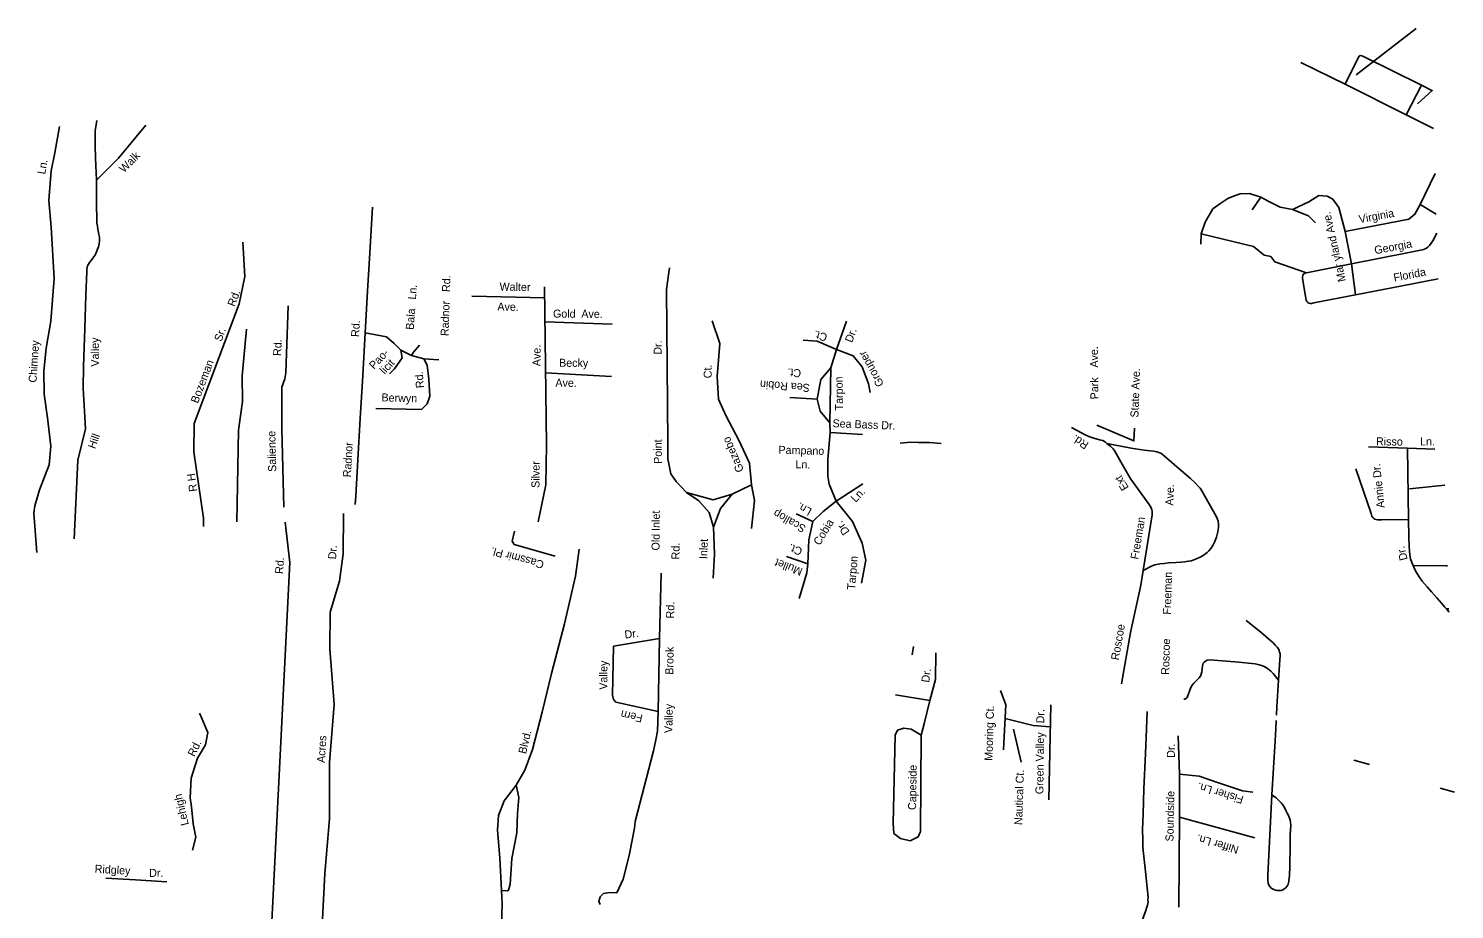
# Model space of a CAD drawing. Extents: x 2308163 to 2335412, y -96774 to 127732.
# Drawn here: x 2322562.54 to 2322608.21, y 95031.9 to 95060.1 of the extents above; entities that cross this region are included whole.
import ezdxf

# ---------------------------------------------------------------- set-up
doc = ezdxf.new("R2010")
doc.units = 0
doc.layers.add('Old_Level_10', color=7, linetype='Continuous')
doc.layers.add('Old_Level_35', color=7, linetype='Continuous')

msp = doc.modelspace()

# ---------------------------------------------------------------- linework, layer by layer
at = {"layer": 'Old_Level_10'}
for points in [[(2322606.977, 95060.101), (2322605.057, 95058.622)], [(2322607.499, 95058.133), (2322607.023, 95057.695)], [(2322597.956, 95047.306), (2322597.942, 95046.903), (2322596.749, 95047.408)], [(2322594.328, 95036.621), (2322594.082, 95037.677)]]:
    msp.add_lwpolyline(points, dxfattribs=at)
at = {"layer": 'Old_Level_35'}
for p, q in [((2322603.287, 95059.019), (2322604.701, 95058.32)), ((2322604.701, 95058.32), (2322606.662, 95057.336)), ((2322606.662, 95057.336), (2322607.153, 95058.284)), ((2322607.499, 95058.111), (2322607.153, 95058.284)), ((2322607.538, 95056.896), (2322606.662, 95057.336)), ((2322605.038, 95051.582), (2322604.905, 95052.57)), ((2322568.145, 95044.429), (2322567.842, 95046.55)), ((2322606.733, 95044.389), (2322606.7, 95046.667)), ((2322573.007, 95044.865), (2322573.023, 95045.135)), ((2322568.146, 95044.162), (2322568.145, 95044.429)), ((2322590.842, 95040.059), (2322590.879, 95040.323)), ((2322602.519, 95038.388), (2322602.567, 95039.244)), ((2322598.354, 95037.976), (2322598.364, 95038.242)), ((2322602.504, 95038.124), (2322602.519, 95038.388)), ((2322598.343, 95037.689), (2322598.354, 95037.976)), ((2322602.492, 95037.948), (2322602.481, 95037.684)), ((2322602.465, 95037.3), (2322602.362, 95035.575)), ((2322602.481, 95037.684), (2322602.465, 95037.3)), ((2322605.488, 95036.548), (2322604.983, 95036.677)), ((2322608.207, 95035.662), (2322607.752, 95035.79))]:
    msp.add_line(p, q, dxfattribs=at)
for points in [[(2322607.153, 95058.284), (2322605.292, 95059.204), (2322605.237, 95059.232), (2322605.191, 95059.24), (2322605.152, 95059.216), (2322605.136, 95059.184), (2322604.701, 95058.32)], [(2322563.389, 95056.118), (2322563.538, 95056.965)], [(2322564.722, 95055.246), (2322564.693, 95055.95), (2322564.68, 95056.364), (2322564.675, 95056.536), (2322564.683, 95056.825), (2322564.73, 95057.152)], [(2322566.305, 95057.013), (2322565.427, 95055.948), (2322564.722, 95055.246)], [(2322562.806, 95043.331), (2322562.714, 95044.588), (2322562.742, 95044.825), (2322562.899, 95045.335), (2322563.204, 95046.137), (2322563.264, 95046.729), (2322563.157, 95047.645), (2322563.044, 95048.401), (2322563.03, 95049.135), (2322563.114, 95049.865), (2322563.263, 95050.732), (2322563.37, 95052.096), (2322563.268, 95053.744), (2322563.198, 95054.599), (2322563.271, 95055.547), (2322563.389, 95056.118)], [(2322564.289, 95048.587), (2322564.305, 95049.284), (2322564.343, 95050.503), (2322564.376, 95051.571), (2322564.41, 95052.313), (2322564.411, 95052.4), (2322564.417, 95052.453), (2322564.43, 95052.509), (2322564.463, 95052.562), (2322564.497, 95052.608), (2322564.551, 95052.678), (2322564.608, 95052.755), (2322564.663, 95052.837), (2322564.707, 95052.922), (2322564.755, 95053.04), (2322564.781, 95053.118), (2322564.802, 95053.208), (2322564.813, 95053.29), (2322564.813, 95053.355), (2322564.812, 95053.422), (2322564.8, 95053.504), (2322564.789, 95053.57), (2322564.764, 95053.675), (2322564.749, 95053.77), (2322564.737, 95053.878), (2322564.722, 95054.573), (2322564.722, 95055.246)], [(2322607.097, 95054.447), (2322607.583, 95055.462)], [(2322604.905, 95052.57), (2322604.706, 95053.601), (2322604.5, 95054.371), (2322604.311, 95054.643), (2322604.131, 95054.732), (2322603.867, 95054.758), (2322603.544, 95054.553), (2322603.022, 95054.306), (2322602.626, 95054.386), (2322602.267, 95054.564), (2322602.007, 95054.706), (2322601.646, 95054.818), (2322601.347, 95054.811), (2322601.129, 95054.736), (2322600.944, 95054.659), (2322600.689, 95054.486), (2322600.468, 95054.328), (2322600.221, 95053.905), (2322600.092, 95053.529), (2322600.08, 95053.197)], [(2322602.007, 95054.706), (2322601.728, 95054.301)], [(2322573.023, 95045.135), (2322573.089, 95046.296), (2322573.167, 95047.623), (2322573.249, 95048.997), (2322573.328, 95050.362), (2322573.399, 95051.697), (2322573.476, 95052.922), (2322573.557, 95054.384)], [(2322603.022, 95054.306), (2322603.529, 95054.106), (2322603.754, 95053.883)], [(2322604.706, 95053.601), (2322606.75, 95053.995), (2322606.938, 95054.154), (2322607.097, 95054.447)], [(2322607.624, 95054.157), (2322607.107, 95054.467)], [(2322567.842, 95046.55), (2322567.849, 95047.455), (2322569.293, 95051.291), (2322569.467, 95052.166), (2322569.409, 95053.265)], [(2322600.092, 95053.529), (2322601.77, 95053.123), (2322602.109, 95052.846), (2322602.323, 95052.805), (2322602.45, 95052.635), (2322603.463, 95052.279)], [(2322604.905, 95052.57), (2322606.688, 95052.926), (2322607.065, 95052.995), (2322607.168, 95053.016), (2322607.215, 95053.03), (2322607.27, 95053.053), (2322607.306, 95053.074), (2322607.349, 95053.105), (2322607.402, 95053.154), (2322607.461, 95053.227), (2322607.51, 95053.304), (2322607.643, 95053.55)], [(2322584.467, 95042.511), (2322584.516, 95043.277), (2322584.478, 95044.135), (2322584.336, 95044.614), (2322584.01, 95044.987), (2322583.613, 95045.249), (2322583.286, 95045.598), (2322583.114, 95045.852), (2322583.018, 95046.33), (2322583.013, 95046.849), (2322582.979, 95051.747), (2322583.04, 95052.219), (2322583.071, 95052.443)], [(2322605.038, 95051.582), (2322603.703, 95051.318), (2322603.624, 95051.303), (2322603.589, 95051.303), (2322603.547, 95051.313), (2322603.515, 95051.329), (2322603.477, 95051.361), (2322603.453, 95051.401), (2322603.339, 95052.1), (2322603.34, 95052.154), (2322603.349, 95052.193), (2322603.365, 95052.232), (2322603.381, 95052.25), (2322603.422, 95052.271), (2322603.463, 95052.279), (2322604.905, 95052.57)], [(2322607.689, 95052.088), (2322606.53, 95051.866), (2322605.038, 95051.582)], [(2322576.743, 95051.533), (2322579.074, 95051.476)], [(2322578.865, 95044.306), (2322579.109, 95045.494), (2322579.131, 95046.78), (2322579.07, 95051.829)], [(2322570.716, 95044.779), (2322570.655, 95047.286), (2322570.656, 95048.618), (2322570.756, 95048.885), (2322570.785, 95049.076), (2322570.859, 95051.229)], [(2322579.084, 95050.708), (2322581.229, 95050.634)], [(2322585.699, 95045.492), (2322585.633, 95046.194), (2322585.296, 95046.906), (2322584.872, 95047.71), (2322584.642, 95048.237), (2322584.599, 95048.961), (2322584.681, 95050.018), (2322584.435, 95050.749)], [(2322588.409, 95044.97), (2322588.179, 95045.52), (2322588.143, 95045.769), (2322588.139, 95046.311), (2322588.214, 95047.166), (2322588.202, 95047.482), (2322588.24, 95049.241), (2322588.418, 95049.822), (2322588.743, 95050.736)], [(2322569.212, 95044.314), (2322569.265, 95047.244), (2322569.398, 95048.165), (2322569.382, 95048.989), (2322569.523, 95050.473)], [(2322573.328, 95050.362), (2322574.011, 95050.228), (2322574.252, 95050.017), (2322574.471, 95049.806), (2322574.507, 95049.557), (2322574.269, 95049.204), (2322574.106, 95049.052)], [(2322588.418, 95049.822), (2322587.795, 95050.092), (2322587.345, 95050.13)], [(2322574.471, 95049.806), (2322574.803, 95049.637), (2322574.875, 95049.747), (2322575.059, 95049.97)], [(2322574.803, 95049.637), (2322575.206, 95049.533), (2322575.679, 95049.494)], [(2322588.418, 95049.822), (2322588.953, 95049.623), (2322589.235, 95049.275), (2322589.442, 95048.726), (2322589.5, 95048.453)], [(2322575.206, 95049.533), (2322575.312, 95049.326), (2322575.364, 95048.873), (2322575.391, 95048.33), (2322575.314, 95048.085), (2322575.128, 95047.911), (2322573.661, 95047.939)], [(2322588.24, 95049.241), (2322587.911, 95048.869), (2322587.799, 95048.241), (2322587.899, 95047.854), (2322588.202, 95047.482)], [(2322579.103, 95049.083), (2322581.216, 95048.963)], [(2322564.289, 95048.587), (2322564.374, 95047.286), (2322564.121, 95046.284), (2322564.004, 95043.765)], [(2322587.799, 95048.241), (2322586.92, 95048.294)], [(2322595.939, 95047.329), (2322596.378, 95047.1), (2322596.495, 95047.043), (2322596.658, 95046.991), (2322596.835, 95046.94), (2322596.944, 95046.914), (2322597.03, 95046.866), (2322597.075, 95046.817)], [(2322588.214, 95047.166), (2322589.25, 95047.108)], [(2322591.766, 95046.823), (2322591.391, 95046.846), (2322591.035, 95046.849), (2322590.789, 95046.857), (2322590.461, 95046.829)], [(2322598.236, 95042.757), (2322598.529, 95044.54), (2322598.53, 95044.587), (2322598.523, 95044.648), (2322598.517, 95044.698), (2322598.509, 95044.73), (2322598.497, 95044.761), (2322598.428, 95044.869), (2322597.844, 95045.681), (2322597.74, 95045.856), (2322597.523, 95046.235), (2322597.387, 95046.473), (2322597.335, 95046.569), (2322597.275, 95046.648), (2322597.205, 95046.721), (2322597.075, 95046.817)], [(2322597.075, 95046.817), (2322597.854, 95046.673), (2322598.274, 95046.609), (2322598.57, 95046.571), (2322598.679, 95046.552), (2322598.741, 95046.535), (2322598.802, 95046.508), (2322598.85, 95046.478), (2322598.918, 95046.414), (2322599.393, 95046.003), (2322599.752, 95045.698), (2322599.905, 95045.561), (2322599.99, 95045.466), (2322600.058, 95045.386), (2322600.119, 95045.307), (2322600.208, 95045.132), (2322600.494, 95044.64), (2322600.575, 95044.49), (2322600.605, 95044.415), (2322600.635, 95044.341), (2322600.653, 95044.237), (2322600.653, 95044.137), (2322600.643, 95044.059), (2322600.632, 95043.988), (2322600.588, 95043.82), (2322600.524, 95043.663), (2322600.467, 95043.555), (2322600.41, 95043.47), (2322600.337, 95043.378), (2322600.29, 95043.332), (2322600.249, 95043.295), (2322600.158, 95043.23), (2322600.067, 95043.181), (2322599.967, 95043.133), (2322599.858, 95043.09), (2322599.789, 95043.066), (2322599.683, 95043.047), (2322599.572, 95043.029), (2322599.45, 95043.022), (2322599.29, 95043.012), (2322599.047, 95042.994), (2322598.914, 95042.982), (2322598.771, 95042.962), (2322598.615, 95042.934), (2322598.528, 95042.906), (2322598.236, 95042.757)], [(2322605.457, 95046.71), (2322606.7, 95046.667)], [(2322606.7, 95046.667), (2322607.578, 95046.636)], [(2322606.733, 95044.389), (2322605.872, 95044.378), (2322605.778, 95044.373), (2322605.748, 95044.374), (2322605.7, 95044.383), (2322605.657, 95044.394), (2322605.625, 95044.413), (2322605.587, 95044.45), (2322605.563, 95044.495), (2322605.542, 95044.574), (2322605.052, 95046.009)], [(2322584.478, 95044.135), (2322584.702, 95044.737), (2322585.079, 95045.198), (2322585.699, 95045.492), (2322585.795, 95044.993), (2322585.696, 95044.093)], [(2322588.409, 95044.97), (2322589.264, 95045.528)], [(2322607.897, 95045.486), (2322606.771, 95045.371)], [(2322583.613, 95045.249), (2322584.463, 95045.016), (2322585.079, 95045.198)], [(2322571.775, 95028.028), (2322572.034, 95033.059), (2322572.18, 95034.801), (2322572.185, 95036.605), (2322572.335, 95038.461), (2322572.196, 95040.242), (2322572.208, 95041.415), (2322572.5, 95042.408), (2322572.616, 95043.291), (2322572.632, 95044.58)], [(2322587.504, 95042.97), (2322587.531, 95043.737), (2322587.664, 95044.319), (2322587.13, 95044.563)], [(2322587.664, 95044.319), (2322587.991, 95044.646), (2322588.409, 95044.97), (2322588.928, 95044.32), (2322589.243, 95043.633), (2322589.36, 95043.087), (2322589.222, 95042.347)], [(2322570.18, 95028.329), (2322570.916, 95043.006), (2322570.76, 95044.3)], [(2322606.884, 95042.908), (2322606.84, 95043.011), (2322606.803, 95043.129), (2322606.782, 95043.239), (2322606.763, 95043.38), (2322606.751, 95043.513), (2322606.742, 95043.827), (2322606.733, 95044.389)], [(2322579.407, 95043.215), (2322578.094, 95043.587), (2322578.032, 95043.687), (2322578.102, 95044.017)], [(2322578.457, 95026.574), (2322578.225, 95026.974), (2322578.065, 95027.094), (2322577.711, 95029.152), (2322577.68, 95029.693), (2322577.656, 95030.414), (2322577.713, 95032.081), (2322577.695, 95032.507), (2322577.633, 95033.556), (2322577.566, 95034.442), (2322577.598, 95034.916), (2322577.778, 95035.384), (2322578.155, 95035.878), (2322578.434, 95036.359), (2322578.686, 95037.022), (2322578.99, 95038.222), (2322579.294, 95039.455), (2322579.709, 95041.044), (2322580.056, 95042.57), (2322580.175, 95043.432)], [(2322587.217, 95041.852), (2322587.472, 95042.678), (2322587.504, 95042.97), (2322586.812, 95043.197)], [(2322597.539, 95039.123), (2322597.828, 95040.773), (2322598.161, 95042.281), (2322598.236, 95042.757)], [(2322608.025, 95041.42), (2322608.021, 95041.427), (2322607.953, 95041.523), (2322607.892, 95041.594), (2322607.794, 95041.705), (2322607.641, 95041.874), (2322607.475, 95042.066), (2322607.337, 95042.226), (2322607.174, 95042.411), (2322607.08, 95042.551), (2322606.989, 95042.694), (2322606.929, 95042.805), (2322606.884, 95042.908)], [(2322607.978, 95042.906), (2322607.939, 95042.906), (2322606.884, 95042.908)], [(2322582.798, 95042.663), (2322582.752, 95040.573), (2322581.278, 95040.329), (2322581.248, 95038.759), (2322581.276, 95038.619), (2322581.355, 95038.535), (2322582.712, 95038.242), (2322582.752, 95040.573)], [(2322607.953, 95041.523), (2322608.022, 95041.528)], [(2322602.567, 95039.244), (2322602.615, 95039.908), (2322602.624, 95040.024), (2322602.623, 95040.083), (2322602.608, 95040.143), (2322602.59, 95040.197), (2322602.567, 95040.247), (2322602.529, 95040.301), (2322602.478, 95040.357), (2322602.401, 95040.437), (2322602.323, 95040.501), (2322602.002, 95040.775), (2322601.535, 95041.153)], [(2322591.598, 95040.117), (2322591.587, 95039.265), (2322591.407, 95038.595), (2322590.31, 95038.774)], [(2322599.542, 95038.632), (2322599.567, 95038.636), (2322599.595, 95038.65), (2322599.622, 95038.667), (2322599.642, 95038.69), (2322599.662, 95038.72), (2322599.688, 95038.806), (2322599.72, 95038.89), (2322599.755, 95038.983), (2322599.812, 95039.083), (2322599.86, 95039.146), (2322599.948, 95039.236), (2322600.028, 95039.321), (2322600.069, 95039.375), (2322600.096, 95039.437), (2322600.12, 95039.514), (2322600.129, 95039.607), (2322600.142, 95039.699), (2322600.149, 95039.743), (2322600.159, 95039.782), (2322600.19, 95039.821), (2322600.236, 95039.856), (2322600.284, 95039.878), (2322600.347, 95039.891), (2322600.511, 95039.879), (2322601.299, 95039.814), (2322601.72, 95039.773), (2322601.829, 95039.762), (2322601.954, 95039.737), (2322602.031, 95039.71), (2322602.117, 95039.677), (2322602.214, 95039.615), (2322602.328, 95039.526), (2322602.4, 95039.454), (2322602.567, 95039.244)], [(2322593.673, 95038.91), (2322593.844, 95038.448), (2322593.763, 95037.018)], [(2322568.019, 95038.19), (2322568.037, 95038.149), (2322568.283, 95037.572), (2322568.213, 95037.175), (2322567.95, 95036.746), (2322567.757, 95036.106), (2322567.716, 95035.48), (2322567.763, 95035.193), (2322567.821, 95034.639), (2322567.901, 95034.218), (2322567.792, 95033.803)], [(2322582.712, 95038.242), (2322582.69, 95037.605), (2322582.631, 95037.329), (2322582.562, 95036.979), (2322581.968, 95034.722), (2322581.945, 95034.502), (2322581.785, 95033.681), (2322581.756, 95033.543), (2322581.585, 95032.87), (2322581.382, 95032.435), (2322581.161, 95032.443), (2322580.955, 95032.409), (2322580.845, 95032.307), (2322580.808, 95032.161), (2322580.853, 95032.061)], [(2322591.407, 95038.595), (2322591.223, 95037.845), (2322591.132, 95037.486), (2322591.105, 95034.401), (2322591.036, 95034.231), (2322590.779, 95034.098), (2322590.467, 95034.172), (2322590.252, 95034.336), (2322590.231, 95034.652), (2322590.297, 95037.484), (2322590.366, 95037.639), (2322590.573, 95037.71), (2322590.808, 95037.671), (2322591.132, 95037.486)], [(2322595.22, 95035.409), (2322595.276, 95038.45)], [(2322593.819, 95038.011), (2322594.719, 95037.788), (2322595.263, 95037.751)], [(2322598.187, 95031.42), (2322598.206, 95031.486), (2322598.232, 95031.602), (2322598.257, 95031.704), (2322598.308, 95031.842), (2322598.351, 95031.974), (2322598.376, 95032.045), (2322598.385, 95032.099), (2322598.394, 95032.145), (2322598.387, 95032.215), (2322598.397, 95032.294), (2322598.366, 95032.6), (2322598.316, 95033.117), (2322598.251, 95033.697), (2322598.225, 95033.893), (2322598.223, 95034.15), (2322598.215, 95034.455), (2322598.235, 95034.963), (2322598.262, 95035.76), (2322598.312, 95036.891), (2322598.343, 95037.689)], [(2322599.399, 95036.237), (2322599.359, 95037.465)], [(2322578.155, 95035.878), (2322578.24, 95035.486), (2322578.206, 95034.98), (2322578.185, 95034.359), (2322578.025, 95033.53), (2322577.964, 95032.714), (2322577.909, 95032.519), (2322577.875, 95032.504), (2322577.695, 95032.507)], [(2322599.385, 95031.977), (2322599.402, 95034.861), (2322599.399, 95036.237)], [(2322599.399, 95036.237), (2322600.027, 95036.165), (2322600.617, 95035.963), (2322601.421, 95035.703), (2322601.751, 95035.658)], [(2322602.362, 95035.575), (2322602.229, 95032.999), (2322602.229, 95032.847), (2322602.239, 95032.746), (2322602.267, 95032.678), (2322602.3, 95032.631), (2322602.341, 95032.589), (2322602.374, 95032.566), (2322602.421, 95032.54), (2322602.472, 95032.523), (2322602.528, 95032.508), (2322602.577, 95032.505), (2322602.607, 95032.507), (2322602.653, 95032.515), (2322602.687, 95032.526), (2322602.738, 95032.548), (2322602.774, 95032.572), (2322602.805, 95032.595), (2322602.838, 95032.633), (2322602.862, 95032.671), (2322602.878, 95032.709), (2322602.892, 95032.759), (2322602.9, 95032.796), (2322602.907, 95032.844), (2322602.915, 95032.896), (2322602.924, 95032.99), (2322602.926, 95033.1), (2322602.929, 95033.169), (2322602.942, 95034.069), (2322602.947, 95034.296), (2322602.957, 95034.456), (2322602.963, 95034.592), (2322602.956, 95034.702), (2322602.941, 95034.758), (2322602.922, 95034.827), (2322602.891, 95034.91), (2322602.853, 95034.986), (2322602.81, 95035.073), (2322602.77, 95035.143), (2322602.706, 95035.248), (2322602.653, 95035.319), (2322602.606, 95035.375), (2322602.496, 95035.472), (2322602.362, 95035.575)], [(2322599.402, 95034.861), (2322601.817, 95034.197)], [(2322565.02, 95032.91), (2322565.969, 95032.854), (2322566.976, 95032.785)]]:
    msp.add_lwpolyline(points, dxfattribs=at)

# ---------------------------------------------------------------- texts
at = {"layer": 'Old_Level_10'}
for s, height, rotation, p in [('Walk', 0.2563, 45.3872, (2322565.601, 95055.467)), ('Ln.', 0.2563, 80.1858, (2322563.076, 95055.421)), ('Mar yland Ave.', 0.25632, 102.8292, (2322604.731, 95052.023)), ('Virginia', 0.2563, 10.4931, (2322605.167, 95053.869)), ('Georgia', 0.2563, 10.4813, (2322605.665, 95052.875)), ('Florida', 0.2563, 11.0089, (2322606.281, 95051.998)), ('Bala   Ln.', 0.2563, 85.7542, (2322574.877, 95050.45)), ('Radnor   Rd.', 0.25632, 88.1523, (2322575.994, 95050.254)), ('Walter', 0.2563, 358.7381, (2322577.625, 95051.716)), ('Bozeman       Sr.        Rd.', 0.25632, 69.1948, (2322567.968, 95048.084)), ('Ave.', 0.2563, 358.7381, (2322577.556, 95051.076)), ('Gold', 0.2563, 359.4093, (2322579.338, 95050.849)), ('Ave.', 0.2563, 359.4093, (2322580.245, 95050.842)), ('Rd.', 0.2563, 86.9357, (2322573.128, 95050.222)), ('Chimney', 0.2563, 86.2486, (2322562.799, 95048.761)), ('Valley', 0.2563, 90.4143, (2322564.803, 95049.28)), ('Rd.', 0.2563, 87.6086, (2322570.632, 95049.615)), ('Dr.', 0.2563, 89.4605, (2322582.818, 95049.66)), ('Ct.', 0.2563, 163.8283, (2322588.146, 95050.322)), ('Dr.', 0.2563, 69.3849, (2322588.915, 95050.029)), ('Pao-', 0.2563, 46.9069, (2322573.61, 95049.173)), ('Ave.', 0.2563, 89.5229, (2322578.938, 95049.292)), ('Grouper', 0.2563, 119.423, (2322589.947, 95048.718)), ('Ave.', 0.2563, 90.5704, (2322596.796, 95049.248)), ('licit', 0.2563, 46.9069, (2322573.949, 95049.014)), ('Becky', 0.2563, 359.3952, (2322579.533, 95049.276)), ('Ct.', 0.2563, 91.0081, (2322584.423, 95048.907)), ('Ct.', 0.2563, 175.7151, (2322587.293, 95049.19)), ('State Ave.', 0.2563, 88.0247, (2322598.084, 95047.646)), ('Rd.', 0.2563, 94.3165, (2322575.208, 95048.599)), ('Ave.', 0.2563, 359.3952, (2322579.415, 95048.636)), ('       Sea Robin ', 0.25632, 175.7151, (2322588.237, 95048.669)), ('Tarpon', 0.2563, 90.9688, (2322588.63, 95047.878)), ('Park', 0.2563, 90.5704, (2322596.806, 95048.232)), ('Berwyn', 0.2563, 358.1695, (2322573.844, 95048.168)), ('Sea Bass Dr.', 0.25632, 357.7622, (2322588.286, 95047.34)), ('Hill ', 0.2563, 70.5702, (2322564.679, 95046.629)), ('Salience', 0.2563, 91.3925, (2322570.477, 95045.913)), ('Radnor', 0.2563, 86.7192, (2322572.864, 95045.731)), ('Point', 0.2563, 90.4182, (2322582.826, 95046.168)), ('Gazebo', 0.2563, 113.0823, (2322585.459, 95045.96)), ('Rd.', 0.2563, 147.5672, (2322596.515, 95046.831)), ('Risso', 0.2563, 359.2312, (2322605.693, 95046.761)), ('Ln.', 0.2563, 359.7872, (2322607.106, 95046.758)), ('Pampano ', 0.2563, 358.5677, (2322586.557, 95046.489)), ('Silver', 0.2563, 89.5225, (2322578.905, 95045.395)), ('Ln.', 0.2563, 358.5677, (2322587.101, 95046.027)), ('Annie Dr.', 0.2563, 96.0826, (2322605.973, 95044.765)), ('R H', 0.2563, 97.6871, (2322567.945, 95045.292)), ('Ext', 0.2563, 120.8787, (2322597.786, 95045.404)), ('Ave.', 0.2563, 88.3651, (2322599.204, 95044.827)), ('Ln.', 0.2563, 45.7345, (2322589.028, 95044.915)), ('Old Inlet', 0.2563, 89.4837, (2322582.751, 95043.392)), ('Scallop ', 0.2563, 150.3852, (2322587.463, 95044.167)), ('Ln.', 0.2563, 150.3852, (2322587.652, 95044.715)), ('Cobia', 0.2563, 58.9524, (2322587.881, 95043.536)), ('Dr.', 0.2563, 125.5361, (2322588.85, 95043.998)), ('Freeman', 0.2563, 80.6561, (2322598.081, 95043.095)), ('Inlet', 0.2563, 88.0247, (2322584.277, 95043.115)), ('Dr.', 0.2563, 85.9893, (2322572.391, 95043.105)), ('Cassmir Pl.', 0.25632, 164.8672, (2322579.071, 95043.049)), ('Rd.', 0.2563, 89.4837, (2322583.389, 95043.107)), ('Ct.', 0.2563, 159.1202, (2322587.349, 95043.461)), ('Tarpon', 0.2563, 84.9637, (2322589.008, 95042.126)), ('Dr.', 0.2563, 104.7581, (2322606.712, 95043.11)), ('Rd.', 0.2563, 85.8938, (2322570.692, 95042.636)), ('Mullet', 0.2563, 159.1202, (2322587.355, 95042.815)), ('Freeman', 0.2563, 88.3651, (2322599.124, 95041.336)), ('Rd.', 0.2563, 89.1148, (2322583.218, 95041.217)), ('Roscoe', 0.2563, 79.9866, (2322597.454, 95039.869)), ('Dr.', 0.2563, 7.317, (2322581.646, 95040.571)), ('Roscoe ', 0.2563, 88.3651, (2322599.068, 95039.411)), ('Brook', 0.2563, 89.1145, (2322583.19, 95039.416)), ('Valley', 0.2563, 89.346, (2322581.074, 95038.934)), ('Dr.', 0.2563, 82.1293, (2322591.384, 95039.155)), ('Fern', 0.2563, 167.8001, (2322582.229, 95038.134)), ('Valley', 0.2563, 89.1134, (2322583.161, 95037.548)), ('Mooring Ct.', 0.25632, 88.2612, (2322593.411, 95036.658)), ('Green Valley   Dr.', 0.25632, 89.2964, (2322595.041, 95035.592)), ('Rd.', 0.2563, 63.6699, (2322567.856, 95036.773)), ('Acres', 0.2563, 86.6331, (2322572.032, 95036.589)), ('Blvd.', 0.2563, 76.5539, (2322578.473, 95036.865)), ('Dr.', 0.2563, 89.6449, (2322599.252, 95036.756)), ('Capeside', 0.2563, 89.1012, (2322590.964, 95035.085)), ('Nautical Ct.', 0.25632, 88.0247, (2322594.362, 95034.602)), ('Fisher Ln.', 0.2563, 162.943, (2322601.473, 95035.523)), ('Lehigh', 0.2563, 103.2557, (2322567.679, 95034.62)), ('Soundside ', 0.2563, 88.8548, (2322599.206, 95034.077)), ('Niffer Ln.', 0.2563, 163.6322, (2322601.32, 95033.919)), ('Ridgley', 0.2563, 356.7432, (2322564.658, 95033.08)), ('Dr.', 0.2563, 359.0282, (2322566.404, 95032.948))]:
    msp.add_text(s, height=height, rotation=rotation, dxfattribs=at).set_placement(p)

doc.saveas('drawing.dxf')
